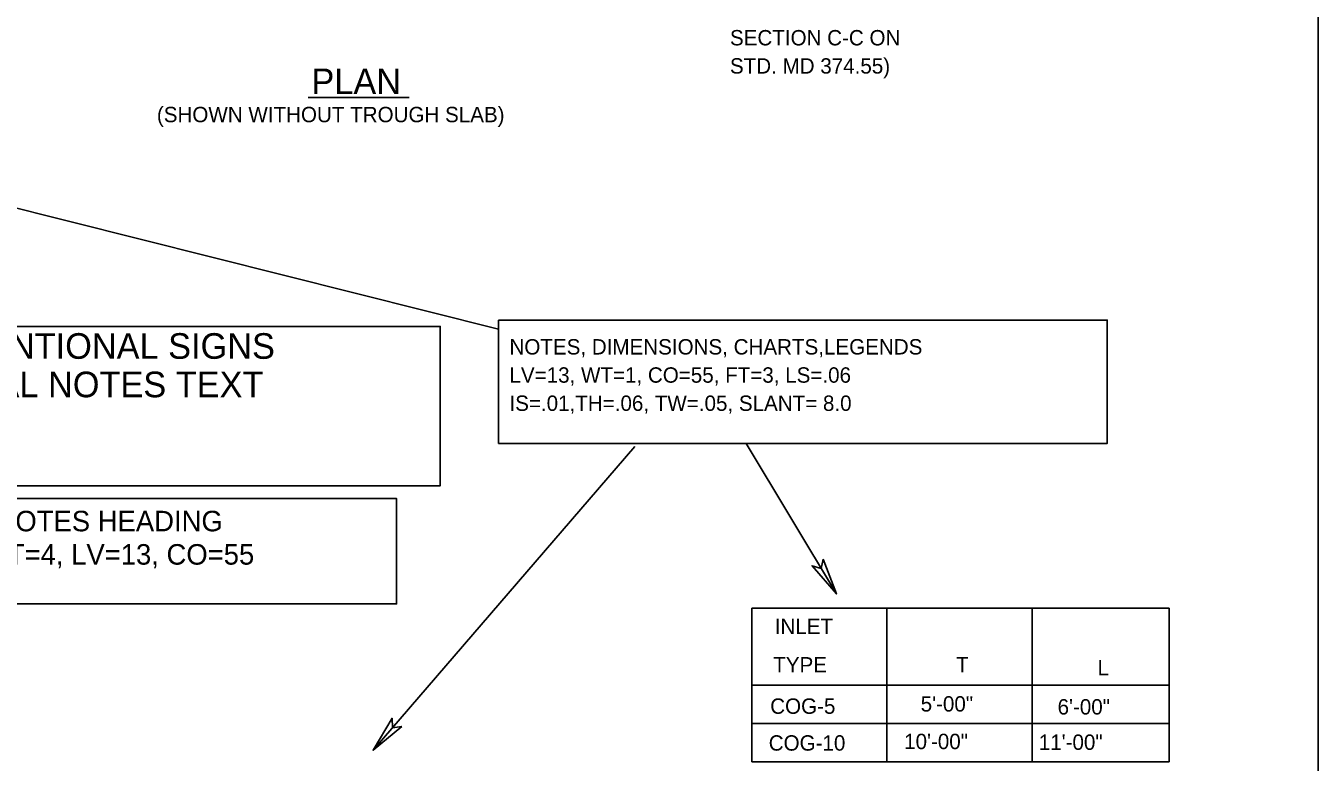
# Model space of a CAD drawing. Extents: x -0.5 to 19.9, y 5.2 to 17.3.
# Drawn here: x 2.73 to 7.77, y 9.26 to 12.13 of the extents above; entities that cross this region are included whole.
import ezdxf

# ---------------------------------------------------------------- set-up
doc = ezdxf.new("R2010")
doc.units = 0
for name, color, linetype in [('DETL-DIMS', 7, 'Continuous'), ('DETL-LINE', 7, 'Continuous'), ('DETL-NOTE', 7, 'Continuous'), ('DETL-TITL', 7, 'Continuous'), ('TTLB-TEXT', 7, 'Continuous')]:
    doc.layers.add(name, color=color, linetype=linetype)

msp = doc.modelspace()

# ---------------------------------------------------------------- linework, layer by layer
at = {"layer": 'DETL-DIMS'}
for p, q in [((4.5743, 10.9505), (1.9064, 11.6206)), ((5.1052, 10.4925), (4.0848, 9.3079)), ((5.5392, 10.5042), (5.8911, 9.9178)), ((5.8911, 9.9178), (5.7959, 10.0274)), ((5.8314, 10.0173), (5.7959, 10.0274)), ((5.8391, 10.0534), (5.8314, 10.0173)), ((5.8911, 9.9178), (5.8391, 10.0534)), ((4.0848, 9.3079), (4.159, 9.4327)), ((4.1605, 9.3958), (4.159, 9.4327)), ((4.0848, 9.3079), (4.1972, 9.3998)), ((4.1972, 9.3998), (4.1605, 9.3958))]:
    msp.add_line(p, q, dxfattribs=at)
for points in [[(5.8391, 10.0534), (5.8911, 9.9178), (5.7959, 10.0274), (5.8314, 10.0173)], [(4.1972, 9.3998), (4.0848, 9.3079), (4.159, 9.4327), (4.1605, 9.3958)]]:
    msp.add_lwpolyline(points, close=True, dxfattribs=at)
at = {"layer": 'DETL-LINE'}
msp.add_lwpolyline([(1.8813, 10.2894), (4.1762, 10.2894), (4.1762, 9.8785), (1.8813, 9.8785)], close=True, dxfattribs=at)
at = {"layer": 'DETL-NOTE'}
for p, q in [((5.5606, 9.8621), (7.1873, 9.8621)), ((5.5606, 9.2621), (5.5606, 9.8621)), ((6.0877, 9.2621), (6.0877, 9.8621)), ((6.6536, 9.2621), (6.6536, 9.8621)), ((7.1873, 9.2621), (7.1873, 9.8621)), ((5.5606, 9.5621), (7.1873, 9.5621)), ((5.5606, 9.4121), (7.1873, 9.4121)), ((5.5606, 9.2621), (7.1873, 9.2621))]:
    msp.add_line(p, q, dxfattribs=at)
for points in [[(4.5743, 10.9863), (6.9467, 10.9863), (6.9467, 10.5047), (4.5743, 10.5047)], [(0.5997, 10.961), (4.3466, 10.961), (4.3466, 10.3397), (0.5997, 10.3397)]]:
    msp.add_lwpolyline(points, close=True, dxfattribs=at)
at = {"layer": 'DETL-TITL'}
msp.add_line((3.8321, 11.855), (4.2261, 11.855), dxfattribs=at)
at = {"layer": 'TTLB-TEXT'}
msp.add_lwpolyline([(0.3943, 16.2906), (7.7685, 16.2906), (7.7685, 5.9375), (0.3943, 5.9375)], close=True, dxfattribs=at)

# ---------------------------------------------------------------- texts
at = {"layer": 'DETL-LINE'}
for s, p in [('LINE UNDER NOTES HEADING ', (1.9358, 10.1619)), ('AA=0,L=0.4, WT=4, LV=13, CO=55', (1.9358, 10.0319))]:
    msp.add_text(s, height=0.08, dxfattribs=at).set_placement(p)
at = {"layer": 'DETL-NOTE'}
for s, height, p in [('SECTION C-C ON', 0.06, (5.4759, 12.0576)), ('STD. MD 374.55)', 0.06, (5.4759, 11.9476)), ('(SHOWN WITHOUT TROUGH SLAB)', 0.06, (3.2423, 11.7579)), ('LEGEND HEADING AND CONVENTIONAL SIGNS', 0.1, (0.6409, 10.8349)), ('NOTES, DIMENSIONS, CHARTS,LEGENDS', 0.06, (4.6165, 10.8517)), ('NOTES  HEADING FOR GENERAL NOTES TEXT ', 0.1, (0.6409, 10.6849)), ('LV=13, WT=1, CO=55, FT=3, LS=.06', 0.06, (4.6165, 10.7417)), ('IS=.01,TH=.06, TW=.05, SLANT= 8.0', 0.06, (4.6165, 10.6317)), ('INLET', 0.06, (5.6504, 9.7607)), ('TYPE', 0.06, (5.6446, 9.6111)), ('T', 0.06, (6.3571, 9.6111)), ('L', 0.06, (6.9084, 9.5994)), ('COG-5', 0.06, (5.6328, 9.4499)), ('5\'-00"', 0.06, (6.2193, 9.4587)), ('6\'-00"', 0.06, (6.7529, 9.4471)), ('10\'-00"', 0.06, (6.1548, 9.3121)), ('11\'-00"', 0.06, (6.6796, 9.3092)), ('COG-10', 0.06, (5.627, 9.3062))]:
    msp.add_text(s, height=height, dxfattribs=at).set_placement(p)
at = {"layer": 'DETL-TITL'}
msp.add_text('PLAN', height=0.1, dxfattribs=at).set_placement((3.8446, 11.8675))

doc.saveas('drawing.dxf')
